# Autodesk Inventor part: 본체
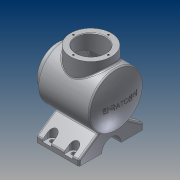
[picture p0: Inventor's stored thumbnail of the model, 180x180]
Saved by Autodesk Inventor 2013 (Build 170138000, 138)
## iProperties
Created: 2017-04
Part Number: 본체
Material: 알루미늄 6061
Document SubType Name: Modeling
Designer: Windows7
Density: 2.71 g/cm^3
Mass: 1670.76 g
Surface Area: 1066.85 cm^2
Volume: 616.517 cm^3
Author: Windows7
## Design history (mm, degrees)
sketch "스케치3"
  geometry: L1 (-54, 0)-(54, 0); L2 (-54, 0)-(-54, 50); L3 (-54, 50)-(42.336, 50); L4 (35.916, 40)-(-44, 40); L5 (-44, 40)-(-44, 0); A1 r 113 centre (-59, 0) between (54, 0) and (42.336, 50); A2 r 103 centre (-59, 0) between (44, 0) and (35.916, 40); 2 further points
  constraints: 10 end point, 4 point on circle, 3 perpendicular, 2 centre point, 2 point on line, 1 coincident, 1 horizontal, 1 horizontal alignment, 1 midpoint
  dimensions: "d13" = 113 radius of A1; "d14" = 100 diameter of L3 L1; "d15" = 10 distance between parallel lines of L5 L2; "d16" = 10 radial gap between concentric circles of A1 A2; "d17" = 10 distance between parallel lines of L4 L3; "d143" = 108 horizontal distance of L1.end L2.end
revolve "회전2" sketch "스케치3" stored, may be unused: angle "d18" = 90 deg
sketch "스케치4"
  geometry: C1 r 50 at (0, 0) reference; C2 r 38 at (0, 0)
  constraints: 1 centre point, 1 coincident
  dimensions: "d19" = 76 diameter of C2
extrude "돌출1" join sketch "스케치4" distance "d20" = 12; taper "d21" = 0 deg
sketch "스케치5"
  geometry: C1 r 38 at (0, 0) reference; C2 r 27 at (0, 0)
  constraints: 1 centre point, 1 coincident
  dimensions: "d22" = 54 diameter of C2
extrude "돌출2" cut sketch "스케치5" distance "d23" = 50; taper "d24" = 0 deg
node "작업 평면2"
sketch "스케치7"
  geometry: L1 (-34, 60)-(46, 60); L2 (46, 60)-(46, -60); L3 (46, -60)-(-34, -60); L4 (-34, -60)-(-34, 60); L5 (54, 50)-(54, -50) reference; 2 further points
  constraints: 8 end point, 2 parallel, 1 horizontal, 1 horizontal alignment, 1 midpoint, 1 perpendicular
  dimensions: "d30" = 8 distance from line of L2.end L5; "d31" = 80 distance of L2.end L3.end; "d32" = 120 distance of L3.end L1.start
extrude "돌출3" join sketch "스케치7" distance "d33" = 10; taper "d34" = 0 deg
sketch "스케치10"
  geometry: L1 (34, -60)-(34, 60) reference; L2 (-46, 60)-(-46, -60) reference; L3 (-46, 5)-(34, 5); L4 (34, 5)-(34, -5); L5 (34, -5)-(-46, -5); L6 (-46, -5)-(-46, 5); 2 further points
  constraints: 8 end point, 2 parallel, 2 point on line, 1 horizontal, 1 horizontal alignment, 1 midpoint, 1 perpendicular
  dimensions: "d35" = 10 distance of L3.end L4.end
extrude "돌출4" join sketch "스케치10" stored distance "d37" = 10; taper "d38" = 0 deg
node "작업 평면3"
sketch "스케치11"
  geometry: L1 (55, 10)-(55, 32.251) reference; L2 (65, 32.251)-(65, 10) reference; L3 (65, 10)-(120, 10) reference; L4 (120, 10)-(120, 0) reference; L5 (120, 0)-(0, 0) reference; L6 (0, 0)-(0, 10) reference; L7 (0, 10)-(55, 10) reference; L8 (0, 10)-(38.416, 36.899); L9 (120, 10)-(81.584, 36.899); C1 r 40 at (60, 82) reference; A1 r 50 centre (60, 82) between (65, 32.251) and (55, 32.251) reference; 1 further point
  constraints: 4 end point, 2 point on circle
  dimensions: "d40" = 55 deg angle of L8 L6; "d41" = 55 deg angle of L9 L4
  node "절단 모서리 투영4"
feature "리브1" dims "d42" = 1, "d43" = 80, "d44" = 0, "d45" = 0, "d46" = 1, "d47" = 1
feature "리브2" dims "d48" = 1, "d49" = 80, "d50" = 0, "d51" = 0, "d52" = 1, "d53" = 1
sketch "스케치12"
  geometry: L1 (120, 0)-(0, 0) reference; C1 r 18 at (60, 0); A1 r 50 centre (60, 82) between (38.416, 36.899) and (81.584, 36.899) reference
  constraints: 1 centre point, 1 midpoint, 1 vertical alignment
  dimensions: "d54" = 36 diameter of C1
extrude "돌출5" cut sketch "스케치12" distance "d56" = 80; taper "d57" = 0 deg
node "작업 평면4"
sketch "스케치13"
  geometry: L1 (-54, -50)-(-54, 50) reference; C1 r 38 at (-4, 0); 1 further point
  constraints: 1 centre point, 1 horizontal alignment
  dimensions: "d121" = 76 diameter of C1; "d123" = 50 distance from line of C1.centre L1
extrude "돌출6" join sketch "스케치13" stored distance "d60" = 80; taper "d61" = 0 deg
sketch "스케치15"
  geometry: L1 (-46, 60)-(-46, 18) reference; C1 r 4 at (-26, 50); 1 further point
  constraints: 1 centre point
  dimensions: "d65" = 8 diameter of C1; "d67" = 50 vertical distance of point (0, 0) C1.centre; "d76" = 20 distance from line of C1.centre L1
extrude "돌출8" cut sketch "스케치15" distance "d69" = 6; taper "d70" = 0 deg
sketch "스케치16"
  geometry: L1 (-8, 0)-(-8, 10); L2 (8, 0)-(8, 10); L3 (-8, 10)-(8, 10); C1 r 4 at (0, 0) reference; A1 r 8 centre (0, 0) between (-8, 0) and (8, 0); 1 further point
  constraints: 6 end point, 2 point on circle, 2 tangent, 1 centre point, 1 coincident, 1 parallel, 1 vertical
  dimensions: "d71" = 8 radius of A1; "d72" = 10 distance of L1.start L1.end; "d73" = 10 distance of L2.start L2.end
extrude "돌출9" cut sketch "스케치16" distance "d74" = 20; taper "d75" = 0 deg
sketch "스케치17" dims "d83" = 65
  geometry: L1 (0, 0)-(0, 32.5); C1 r 38 at (0, 0) reference
  constraints: 2 end point, 1 coincident, 1 vertical, 1 vertical alignment, 2 other
hole "구멍1" sketch "스케치17" at (0, 32.5) diameter "d84" = 3.242; stored, may be unused: countersink angle "d88" = 90 deg, drill point angle "d90" = 120 deg; dims "d85" = 8, "d86" = 4, "d87" = 2, "d89" = 10
node "작업 평면5"
sketch "스케치19"
  geometry: 2 further points
  constraints: 1 coincident, 1 other
feature "엠보싱1" sketch "스케치19" dims "d22" = 54, "d105" = 0.5, "d106" = 0
fillet "모깎기1" dims "d107" = 3
fillet "모깎기2" dims "d108" = 3
fillet "모깎기3" dims "d112" = 3
chamfer "모따기1" distance "d113" = 1; stored, may be unused: second distance "d114" = 2, angle "d115" = 45 deg
fillet "모깎기4" dims "d120" = 3
sketch "스케치20"
  geometry: C1 r 38 at (0, 0) reference; C2 r 27 at (0, 0); 1 further point
  constraints: 1 centre point, 1 coincident
  dimensions: "d124" = 54 diameter of C2
extrude "돌출10" cut sketch "스케치20" distance "d125" = 50; taper "d126" = 0 deg
sketch "스케치21" dims "d127" = 65
  geometry: L1 (0, 0)-(0, 32.5); C1 r 27 at (0, 0) reference; C2 r 38 at (0, 0) reference; 1 further point
  constraints: 2 end point, 2 vertical alignment, 1 coincident, 2 other
hole "구멍3" sketch "스케치21" at (0, 32.5) diameter "d128" = 3.242; stored, may be unused: countersink angle "d132" = 90 deg, drill point angle "d134" = 120 deg; dims "d129" = 8, "d130" = 4, "d131" = 2, "d133" = 10
chamfer "모따기2" distance "d138" = 1; stored, may be unused: second distance "d139" = 2, angle "d140" = 45 deg
fillet "모깎기5" dims "d141" = 3
node "솔리드2"
pattern_circular "원형 패턴1" dims angle "d92" = 360 deg
pattern_linear "직사각형 패턴2"
mirror "대칭1"
pattern_circular "원형 패턴4" dims angle "d145" = 360 deg
other parameters: "d29" = -82, "d58" = -147, "d116" = 0.5, "d117" = 2, "d118" = 0
